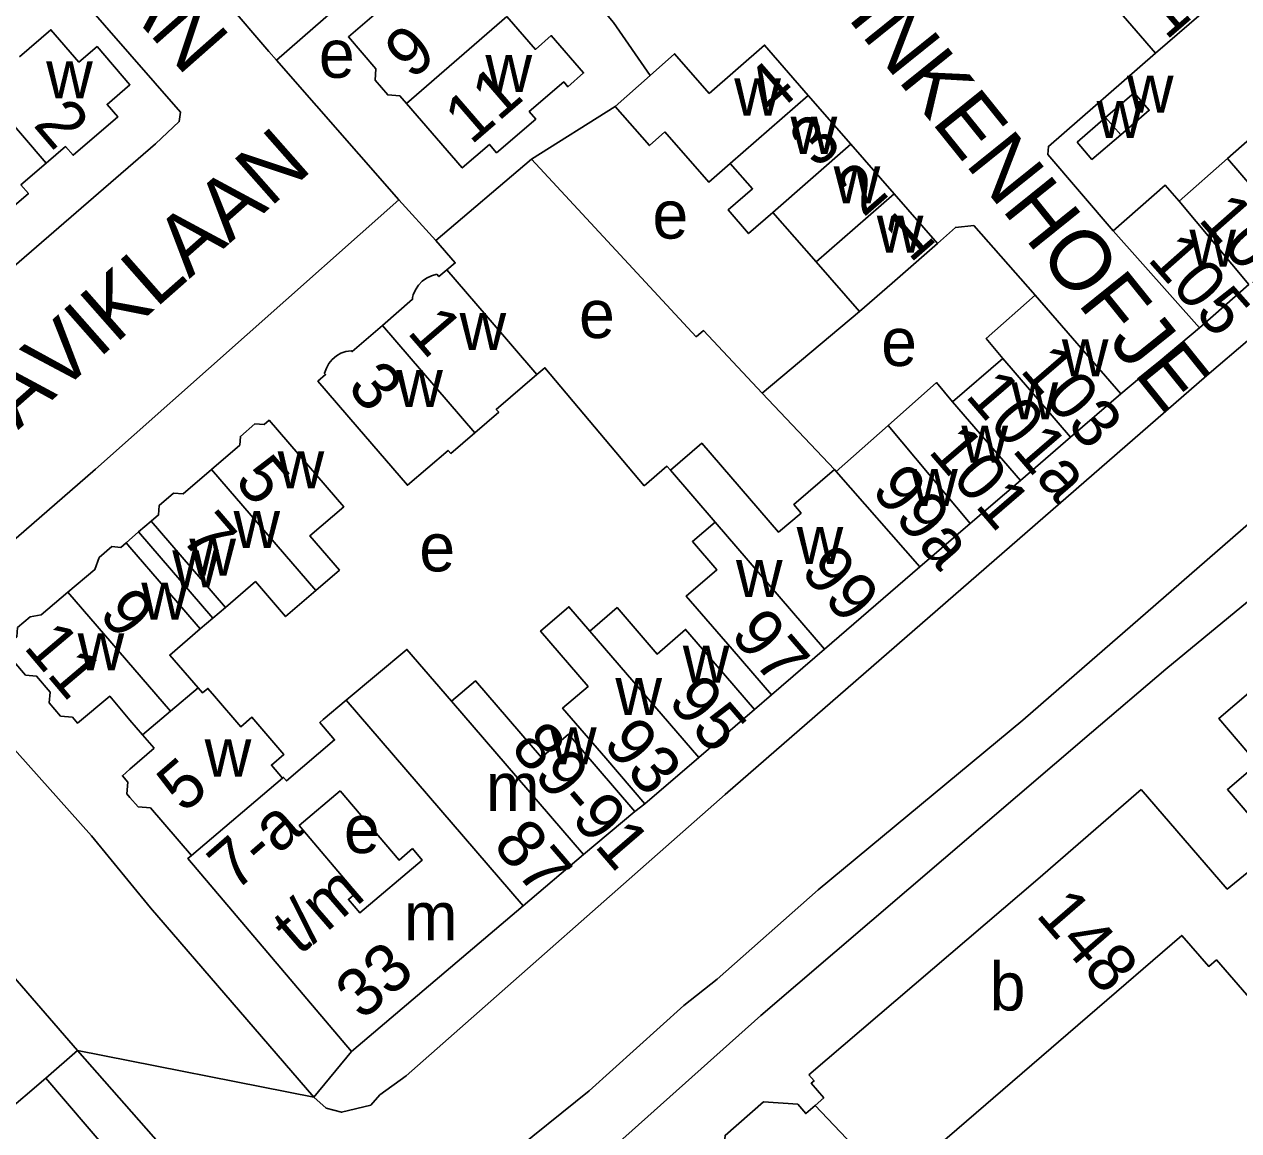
# Model space of a CAD drawing. Extents: x 161775 to 163181, y 382878 to 383925.
# Drawn here: x 162491.2 to 162592, y 383405.1 to 383496.9 of the extents above; entities that cross this region are included whole.
import ezdxf

# ---------------------------------------------------------------- set-up
doc = ezdxf.new("R2010")
doc.units = 0
for name, color, linetype in [('BLT_Basislijn', 7, 'Continuous'), ('BLT_Bebouwing', 7, 'Continuous'), ('BLT_Centroide', 7, 'Continuous'), ('BLT_Huisnummer', 7, 'Continuous'), ('BLT_Huisnummer_ tussenligend', 7, 'Continuous'), ('BLT_Huisnummer_reeks', 7, 'Continuous'), ('BLT_Onderdoorgang_en_onderverdeling', 7, 'Continuous'), ('BLT_Onderverdeling_panden', 7, 'Continuous'), ('BLT_Plantopo', 7, 'Continuous'), ('BLT_Straatnaam', 7, 'Continuous'), ('BLT_Vlakafsluiter', 7, 'Continuous')]:
    doc.layers.add(name, color=color, linetype=linetype)

msp = doc.modelspace()

# ---------------------------------------------------------------- linework, layer by layer
at = {"layer": 'BLT_Basislijn'}
for p, q in [((162512.15, 383493.92), (162524.24, 383504.51)), ((162508.06, 383498.69), (162511.52, 383494.65)), ((162512.15, 383493.92), (162511.52, 383494.65)), ((162522.29, 383482.35), (162512.15, 383493.92)), ((162533.31, 383485.72), (162540.24, 383490.09)), ((162525.36, 383478.98), (162533.31, 383485.72)), ((162546.98, 383470.99), (162533.31, 383485.72)), ((162525.36, 383478.98), (162522.29, 383482.35)), ((162560.51, 383473.08), (162552.44, 383466.31)), ((162588.72, 383471.72), (162582.18, 383466.24)), ((162585.93, 383443.4), (162596.07, 383451.8)), ((162579.18, 383443.64), (162582.96, 383446.93)), ((162579.77, 383438.14), (162585.93, 383443.4)), ((162552.32, 383414.66), (162579.77, 383438.14)), ((162541.88, 383431.61), (162542.72, 383432.24)), ((162538.96, 383402.74), (162552.32, 383414.66)), ((162493.01, 383409.47), (162495.64, 383411.76)), ((162518.39, 383411.69), (162515.26, 383407.9))]:
    msp.add_line(p, q, dxfattribs=at)
for points in [[(162515.26, 383407.9), (162516.28, 383406.99), (162517.56, 383406.64), (162519.98, 383407.22), (162520.74, 383408.09), (162522.92, 383409.68), (162549.37, 383433.01), (162589.33, 383467.77), (162592.9, 383470.8), (162593.79, 383471.34), (162600, 383476.66), (162604.65, 383480.65), (162607.41, 383483.28), (162627.95, 383500.95), (162641.5, 383512.26), (162643.67, 383514.55), (162644.53, 383516.57), (162644.72, 383519.48), (162643.92, 383522.1)], [(162476.85, 383520.93), (162504.19, 383489.63), (162504.09, 383488.84), (162502.12, 383486.99), (162474.34, 383462.96)], [(162536.86, 383511.2), (162532.47, 383507.43), (162532.2, 383506.5), (162540.12, 383497.07), (162543.14, 383492.66)], [(162581.55, 383479.77), (162576.13, 383486.1), (162576.19, 383486.77), (162585.06, 383494.51)], [(162522.29, 383482.35), (162497.13, 383460), (162482.05, 383446.88)], [(162575.08, 383474.43), (162569.99, 383480.21), (162568.47, 383480.06), (162566.99, 383478.73)], [(162526.29, 383476.53), (162526.98, 383477.11), (162525.36, 383478.98)], [(162582.96, 383446.93), (162600, 383461.75), (162618.76, 383478.18), (162621.79, 383474.45)], [(162542.66, 383458.62), (162534.42, 383468.41), (162533.76, 383467.86)], [(162482.05, 383446.88), (162489.74, 383437.51), (162496.82, 383429.59), (162501.69, 383423.6), (162515.26, 383407.9)], [(162529.74, 383393.65), (162528.31, 383395.37), (162527.63, 383397.03), (162527.72, 383398.49), (162529.4, 383401.09), (162531.15, 383402.83), (162538.09, 383408.43), (162545.95, 383415.51), (162548.7, 383417.68), (162557.09, 383425.11), (162574.06, 383439.18), (162579.18, 383443.64)], [(162495.64, 383411.76), (162472.36, 383438.61), (162471.64, 383438.47), (162459.3, 383427.81), (162454.29, 383423.76), (162452.92, 383422.41), (162420.3, 383394.84), (162416.34, 383390.96), (162412.36, 383387.52), (162403.8, 383380.46), (162382.22, 383361.95), (162376.07, 383356.94), (162357.64, 383341.11), (162357.5, 383340.43), (162364.56, 383332.99), (162388.13, 383309.03), (162393.36, 383303.95)], [(162503.48, 383397.25), (162505.99, 383399.59), (162505.83, 383400.2), (162495.64, 383411.76)]]:
    msp.add_lwpolyline(points, dxfattribs=at)
at = {"layer": 'BLT_Bebouwing'}
for p, q in [((162585.06, 383494.51), (162581.5, 383498.64)), ((162540.24, 383490.09), (162543.14, 383492.66)), ((162556.27, 383491.01), (162559.81, 383486.96)), ((162580.92, 383489.17), (162582.18, 383487.74)), ((162591.04, 383485.78), (162595.05, 383489.31)), ((162559.81, 383486.96), (162563.4, 383482.84)), ((162587.03, 383482.24), (162591.04, 383485.78)), ((162563.4, 383482.84), (162566.99, 383478.73)), ((162556.92, 383477.19), (162553.33, 383481.3)), ((162588.72, 383471.72), (162581.55, 383479.77)), ((162560.51, 383473.08), (162556.92, 383477.19)), ((162592.82, 383475.33), (162588.72, 383471.72)), ((162575.08, 383474.43), (162582.18, 383466.24)), ((162572.4, 383469.18), (162568.23, 383465.59)), ((162552.44, 383466.31), (162558.43, 383459.96)), ((162582.18, 383466.24), (162578.02, 383462.66)), ((162562.88, 383463.61), (162558.59, 383459.8)), ((162578.02, 383462.66), (162573.86, 383459.07)), ((162544.83, 383459.91), (162548.53, 383455.61)), ((162558.59, 383459.8), (162558.43, 383459.96)), ((162573.86, 383459.07), (162569.69, 383455.48)), ((162569.69, 383455.48), (162565.53, 383451.89)), ((162565.53, 383451.89), (162557.62, 383445.07)), ((162557.62, 383445.07), (162553.21, 383441.27)), ((162517.93, 383440.83), (162516.04, 383439.23)), ((162553.21, 383441.27), (162551.81, 383440.07)), ((162551.81, 383440.07), (162547.18, 383436.08)), ((162501.05, 383437.96), (162502.01, 383436.84)), ((162537.62, 383428.03), (162541.88, 383431.61)), ((162537.62, 383428.03), (162532.63, 383423.76)), ((162532.63, 383423.76), (162518.39, 383411.69)), ((162556.83, 383407.2), (162557.57, 383407.84))]:
    msp.add_line(p, q, dxfattribs=at)
for points in [[(162524.24, 383504.51), (162525.87, 383502.48), (162523.58, 383500.49), (162522.97, 383501.19), (162521.59, 383500), (162519.88, 383498.52), (162520.44, 383497.87), (162518.12, 383495.86), (162520.4, 383493.22), (162520.33, 383492.26), (162521.38, 383491.05), (162522.39, 383490.97), (162522.93, 383490.34)], [(162588.05, 383504.15), (162591.54, 383500.1), (162591.43, 383500), (162588.85, 383497.77), (162585.06, 383494.51)], [(162522.93, 383490.34), (162527.56, 383484.99), (162529.82, 383486.94), (162530.41, 383486.25), (162533.66, 383489.05), (162533.12, 383489.66), (162535.98, 383492.13), (162536.32, 383491.73), (162537.63, 383492.87), (162534.95, 383495.97), (162533.63, 383494.82), (162531.27, 383497.55)], [(162490.83, 383494.22), (162493.44, 383496.46), (162495.76, 383493.77), (162497.27, 383495.06), (162499.99, 383491.89), (162498.1, 383490.26), (162498.98, 383489.23), (162495.28, 383486.04), (162494.66, 383486.76), (162493.05, 383485.38)], [(162548.05, 383491.18), (162552.64, 383495.18), (162556.27, 383491.01)], [(162543.14, 383492.66), (162545.18, 383494.46), (162548.05, 383491.18)], [(162493.05, 383485.38), (162490.96, 383483.58), (162491.57, 383482.86), (162487.83, 383479.65), (162486, 383481.77), (162485.72, 383481.52), (162482.46, 383485.32), (162481.42, 383486.53), (162484.03, 383488.76), (162482.46, 383490.59), (162484.56, 383492.38)], [(162582.18, 383487.74), (162584.55, 383489.78), (162583.31, 383491.23), (162580.92, 383489.17)], [(162540.24, 383490.09), (162543.1, 383486.85), (162544.38, 383487.98)], [(162580.92, 383489.17), (162578.56, 383487.14)], [(162549.8, 383485.37), (162548.02, 383483.81), (162544.38, 383487.98)], [(162578.56, 383487.14), (162579.8, 383485.7), (162582.18, 383487.74)], [(162553.33, 383481.3), (162551.32, 383479.55), (162549.62, 383481.51), (162551.64, 383483.26), (162549.8, 383485.37)], [(162581.55, 383479.77), (162585.86, 383483.57), (162587.03, 383482.24)], [(162566.99, 383478.73), (162563.23, 383475.44), (162560.51, 383473.08)], [(162525.45, 383476.17), (162525.02, 383476.05), (162524.61, 383475.85), (162524.24, 383475.59), (162523.93, 383475.26), (162523.68, 383474.89), (162523.49, 383474.47), (162523.43, 383474.23)], [(162526.29, 383476.53), (162525.63, 383475.97), (162525.45, 383476.17)], [(162533.76, 383467.86), (162529.55, 383472.74), (162526.29, 383476.53)], [(162523.43, 383474.23), (162523.45, 383474.09), (162520.94, 383471.92)], [(162575.08, 383474.43), (162571.03, 383470.84), (162572.4, 383469.18)], [(162520.94, 383471.92), (162518.42, 383469.75), (162518.35, 383469.83)], [(162552.44, 383466.31), (162547.58, 383471.5), (162546.98, 383470.99)], [(162518.35, 383469.83), (162517.91, 383469.76), (162517.5, 383469.61), (162517.12, 383469.39), (162516.78, 383469.11), (162516.51, 383468.77), (162516.29, 383468.38), (162516.15, 383467.96), (162516.15, 383467.94)], [(162516.15, 383467.94), (162516.22, 383467.85), (162515.59, 383467.3), (162518.85, 383463.52), (162523.02, 383458.66), (162526.39, 383461.56), (162526.61, 383461.3), (162528.6, 383463.02)], [(162533.76, 383467.86), (162530.39, 383464.96), (162530.59, 383464.73), (162528.6, 383463.02)], [(162568.23, 383465.59), (162566.9, 383467.18), (162562.88, 383463.61)], [(162506.76, 383459.98), (162509.11, 383462), (162509.16, 383462.71), (162510.37, 383463.76), (162511.12, 383463.7), (162511.54, 383464.06), (162514.8, 383460.27), (162517.73, 383456.88), (162514.93, 383454.47), (162517.38, 383451.62), (162515.43, 383449.93)], [(162558.43, 383459.96), (162555.07, 383457.07), (162555.67, 383456.36), (162553.81, 383454.76), (162547.43, 383462.15), (162544.83, 383459.91)], [(162501.76, 383455.68), (162502.37, 383456.21), (162502.43, 383456.99), (162503.62, 383458.02), (162504.42, 383457.96), (162506.76, 383459.98)], [(162544.83, 383459.91), (162544.54, 383460.24), (162542.66, 383458.62)], [(162499.69, 383453.89), (162500.72, 383454.79)], [(162500.72, 383454.79), (162501.76, 383455.68)], [(162548.53, 383455.61), (162546.65, 383453.99), (162548.67, 383451.64), (162546.15, 383449.47), (162549.95, 383445.06), (162553.21, 383441.27)], [(162494.85, 383449.79), (162497.08, 383451.67), (162497.44, 383452.67), (162498.5, 383453.57), (162499.23, 383453.51), (162499.69, 383453.89)], [(162501.05, 383437.96), (162499.99, 383439.18), (162498.32, 383441.16), (162495.66, 383438.92), (162495.23, 383439.42), (162494.24, 383439.51), (162493.31, 383440.61), (162493.38, 383441.5), (162492.26, 383442.82), (162491.34, 383442.9), (162490.37, 383444.04), (162490.45, 383444.97), (162489.96, 383445.55), (162490.61, 383446.1), (162490.67, 383446.86), (162491.72, 383447.75), (162492.63, 383447.91), (162494.85, 383449.79)], [(162515.43, 383449.93), (162512.91, 383447.77), (162510.41, 383450.67), (162507.93, 383448.53)], [(162507.93, 383448.53), (162506.88, 383447.64)], [(162542.72, 383432.24), (162539.46, 383436.02), (162535.89, 383440.16), (162538, 383441.98), (162534.06, 383446.56), (162536.41, 383448.58), (162538.15, 383446.56)], [(162538.15, 383446.56), (162540.41, 383448.51), (162543.73, 383444.66), (162546.09, 383446.7), (162548.55, 383443.86), (162551.81, 383440.07)], [(162505.81, 383446.74), (162503.3, 383444.58), (162505.65, 383441.85)], [(162506.88, 383447.64), (162505.81, 383446.74)], [(162526.67, 383440.74), (162522.97, 383445.04), (162517.93, 383440.83)], [(162507.02, 383441.16), (162506.46, 383441.81), (162506.02, 383441.43), (162505.65, 383441.85)], [(162541.88, 383431.61), (162538.67, 383435.33), (162536.38, 383438), (162534.15, 383436.08), (162528.66, 383442.45), (162526.67, 383440.74)], [(162512.65, 383434.36), (162511.73, 383435.45), (162512.77, 383436.34), (162510.12, 383439.41), (162509.21, 383438.62), (162507.02, 383441.16)], [(162502.01, 383436.84), (162500, 383435.1), (162499.37, 383434.57), (162499.82, 383434.04), (162499.74, 383433.06), (162499.99, 383432.75), (162500.69, 383431.98), (162501.7, 383431.91), (162505.11, 383427.96)], [(162547.18, 383436.08), (162542.72, 383432.24)], [(162517.45, 383433.32), (162514.04, 383430.43), (162518.76, 383424.85), (162518.12, 383424.3), (162519.07, 383423.18), (162524.25, 383427.56), (162523.44, 383428.52)], [(162517.45, 383433.32), (162522.32, 383427.57), (162523.44, 383428.52)], [(162556.32, 383409.74), (162575.3, 383425.99), (162583.88, 383433.41)], [(162583.88, 383433.41), (162591.02, 383425.16), (162595.68, 383428.96), (162600, 383423.97), (162604.73, 383418.5)], [(162518.39, 383411.69), (162504.81, 383427.71), (162505.11, 383427.96)], [(162609.66, 383396.77), (162600, 383407.9), (162590.12, 383419.29), (162589.48, 383418.74), (162587.25, 383421.31), (162579.44, 383414.56), (162563.18, 383400.54)], [(162493.01, 383409.47), (162489.4, 383406.37), (162474.31, 383393.57)], [(162493.01, 383409.47), (162503.48, 383397.25)], [(162557.57, 383407.84), (162556.52, 383409.05), (162556.75, 383409.25), (162556.32, 383409.74)], [(162590.31, 383378.05), (162587.43, 383378.25), (162586.62, 383379.19), (162585.13, 383377.9), (162585.95, 383376.95), (162584.9, 383376.04), (162582.91, 383376.18), (162580.45, 383379.02), (162581.26, 383379.72), (162579.93, 383381.26), (162575.63, 383377.53), (162563.37, 383378.41), (162546, 383398.48), (162546.21, 383401.48), (162548.16, 383403.16), (162549.24, 383403.08), (162549.36, 383404.73), (162552.56, 383407.51), (162555.39, 383407.31), (162556.06, 383406.53), (162556.83, 383407.2)]]:
    msp.add_lwpolyline(points, dxfattribs=at)
at = {"layer": 'BLT_Onderdoorgang_en_onderverdeling'}
for points in [[(162507.93, 383448.53), (162505.02, 383451.9), (162501.76, 383455.68)], [(162499.69, 383453.89), (162500, 383453.53), (162502.94, 383450.1), (162505.81, 383446.74)]]:
    msp.add_lwpolyline(points, dxfattribs=at)
at = {"layer": 'BLT_Onderverdeling_panden'}
for p, q in [((162522.93, 383490.34), (162531.27, 383497.55)), ((162493.05, 383485.38), (162487.74, 383491.57)), ((162549.8, 383485.37), (162556.27, 383491.01)), ((162553.33, 383481.3), (162559.81, 383486.96)), ((162591.04, 383485.78), (162596.91, 383478.94)), ((162556.92, 383477.19), (162563.4, 383482.84)), ((162587.03, 383482.24), (162592.82, 383475.33)), ((162520.94, 383471.92), (162528.6, 383463.02)), ((162578.02, 383462.66), (162572.4, 383469.18)), ((162573.86, 383459.07), (162568.23, 383465.59)), ((162569.69, 383455.48), (162562.88, 383463.61)), ((162506.76, 383459.98), (162515.43, 383449.93)), ((162558.59, 383459.8), (162565.53, 383451.89)), ((162500.72, 383454.79), (162506.88, 383447.64)), ((162548.53, 383455.61), (162557.62, 383445.07)), ((162494.85, 383449.79), (162503.37, 383439.92)), ((162547.18, 383436.08), (162538.15, 383446.56)), ((162503.37, 383439.92), (162505.65, 383441.85)), ((162532.63, 383423.76), (162517.93, 383440.83)), ((162526.67, 383440.74), (162537.62, 383428.03)), ((162503.37, 383439.92), (162501.05, 383437.96)), ((162556.83, 383407.2), (162563.18, 383400.54))]:
    msp.add_line(p, q, dxfattribs=at)
for points in [[(162516.04, 383439.23), (162515.75, 383438.98), (162516.98, 383437.53), (162512.99, 383434.14), (162512.74, 383434.43), (162512.65, 383434.36)], [(162512.65, 383434.36), (162505.11, 383427.96)]]:
    msp.add_lwpolyline(points, dxfattribs=at)
at = {"layer": 'BLT_Plantopo'}
msp.add_lwpolyline([(162599.14, 383454.21), (162594.44, 383450.2), (162598.08, 383445.94), (162590.33, 383439.32), (162593.54, 383435.55), (162591.04, 383433.42), (162596.84, 383426.62), (162599.41, 383428.81), (162616.98, 383408.21), (162615.12, 383406.61), (162613.89, 383408.06), (162592.49, 383389.8), (162599.09, 383382.08), (162625.13, 383404.55), (162626.34, 383403.15), (162637.73, 383412.98), (162632.5, 383419.05), (162626.02, 383413.46), (162605.37, 383437.4), (162611.23, 383442.45)], close=True, dxfattribs=at)
at = {"layer": 'BLT_Vlakafsluiter'}
msp.add_line((162515.26, 383407.9), (162495.64, 383411.76), dxfattribs=at)

# ---------------------------------------------------------------- texts
at = {"layer": 'BLT_Centroide'}
for s, p in [('e', (162515.67, 383492.47)), ('w', (162529.49, 383491.28)), ('w', (162493.05, 383490.77)), ('w', (162550.13, 383489.34)), ('w', (162582.7, 383489.58)), ('w', (162580.18, 383487.48)), ('w', (162554.8, 383486.16)), ('w', (162558.37, 383482.06)), ('e', (162543.34, 383479.13)), ('w', (162561.95, 383477.97)), ('w', (162587.88, 383476.8)), ('e', (162537.25, 383470.88)), ('w', (162527.34, 383469.89)), ('e', (162562.31, 383468.56)), ('w', (162577.3, 383467.7)), ('w', (162522.09, 383465.16)), ('w', (162573.12, 383464.12)), ('w', (162568.97, 383460.53)), ('w', (162512.25, 383458.42)), ('w', (162564.8, 383456.94)), ('w', (162508.59, 383453.47)), ('w', (162555.3, 383452.14)), ('w', (162504.93, 383451.16)), ('e', (162524, 383451.52)), ('w', (162503.51, 383450.2)), ('w', (162550.27, 383449.39)), ('w', (162500.94, 383447.52)), ('w', (162495.66, 383443.31)), ('w', (162545.86, 383442.28)), ('w', (162540.27, 383439.59)), ('w', (162534.84, 383435.5)), ('w', (162506.2, 383434.5)), ('m', (162529.52, 383431.64)), ('e', (162517.75, 383428.15)), ('m', (162522.72, 383420.92)), ('b', (162571.31, 383415.09))]:
    msp.add_text(s, height=4, dxfattribs=at).set_placement(p)
at = {"layer": 'BLT_Huisnummer'}
for s, rotation, p in [('13', 40.7504, (162585.95, 383495.53)), ('9', 40.8369, (162523.37, 383492.22)), ('11', 40.8302, (162528.3, 383486.84)), ('4', 41.1057, (162553.29, 383489.17)), ('2', 310.6752, (162491.9, 383488.54)), ('1', 41.1051, (162564.72, 383477.04)), ('105', 311.404, (162584.32, 383477.39)), ('1', 310.7124, (162522.91, 383471.34)), ('103', 310.7629, (162573.75, 383468.17)), ('3', 310.7124, (162517.92, 383466.75)), ('101a', 310.7629, (162569.21, 383466.06)), ('101', 310.7629, (162566.14, 383461.46)), ('5', 310.7666, (162508.58, 383458.96)), ('99a', 310.7586, (162561.4, 383458.2)), ('7', 310.7666, (162504.12, 383454.27)), ('99', 310.752, (162555.53, 383451.49)), ('9', 310.7666, (162497.32, 383447.93)), ('97', 310.7617, (162549.71, 383446.22)), ('11', 310.2228, (162491.1, 383445.21)), ('93', 310.7666, (162539.13, 383437.17)), ('5', 40.7648, (162504.46, 383431.38)), ('87', 310.7658, (162530, 383428.76))]:
    msp.add_text(s, height=4, rotation=rotation, dxfattribs=at).set_placement(p)
at = {"layer": 'BLT_Huisnummer_ tussenligend'}
for s, rotation, p in [('3', 41.1051, (162556.96, 383484.85)), ('2', 41.1044, (162560.84, 383480.83)), ('107', 311.404, (162588.53, 383480.68)), ('95', 310.7666, (162544.52, 383440.7))]:
    msp.add_text(s, height=4, rotation=rotation, dxfattribs=at).set_placement(p)
at = {"layer": 'BLT_Huisnummer_reeks'}
for s, rotation, p in [('89-91', 310.7731, (162531.46, 383436.84)), ('7-a', 40.8846, (162508.69, 383424.86)), ('t/m', 40.8846, (162514.06, 383419.59)), ('148', 310.8837, (162575.06, 383422.99)), ('33', 40.8846, (162519.28, 383414.19))]:
    msp.add_text(s, height=4, rotation=rotation, dxfattribs=at).set_placement(p)
at = {"layer": 'BLT_Straatnaam'}
for s, rotation, p in [('GAAILAAN', 311.4755, (162482.57, 383517.57)), ('VINKENHOFJE', 308.8135, (162556.64, 383500.95)), ('HAVIKLAAN', 41.42, (162487.09, 383460.03))]:
    msp.add_text(s, height=5, rotation=rotation, dxfattribs=at).set_placement(p)

doc.saveas('drawing.dxf')
